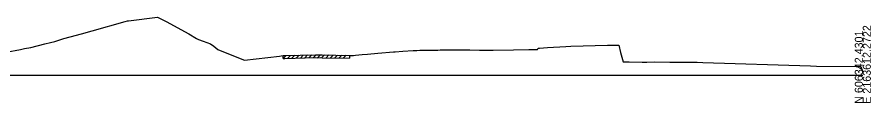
# Model space of a CAD drawing. Extents: x -26 to 6803, y -10 to 19606.
# Drawn here: x 6504.2 to 6802.8, y 4990.3 to 5020.3 of the extents above; entities that cross this region are included whole.
import ezdxf

# ---------------------------------------------------------------- set-up
doc = ezdxf.new("R2010")
doc.units = 0
for name, color, linetype in [('RD_GPK_XS_Cell', 7, 'Continuous'), ('RD_XS_ExGround', 7, 'Continuous'), ('RD_XS_ExPaveRet', 7, 'Continuous')]:
    doc.layers.add(name, color=color, linetype=linetype)

msp = doc.modelspace()

# ---------------------------------------------------------------- linework, layer by layer
at = {"layer": 'RD_GPK_XS_Cell'}
msp.add_line((6400, 5000), (6800, 5000), dxfattribs=at)
at = {"layer": 'RD_XS_ExGround'}
msp.add_lwpolyline([(6500.38, 5008), (6505.36, 5008.99), (6506.75, 5009.33), (6508.99, 5009.72), (6513.89, 5010.95), (6515.88, 5011.48), (6517.39, 5011.8), (6520.54, 5012.88), (6522.74, 5013.36), (6526.78, 5014.46), (6530.51, 5015.49), (6542.06, 5018.82), (6542.83, 5019.01), (6543.17, 5019.04), (6553.31, 5020.31), (6556.33, 5018.76), (6564.24, 5014.5), (6567.02, 5012.81), (6567.63, 5012.49), (6569.35, 5011.84), (6571.87, 5011), (6572.97, 5010.16), (6574.48, 5008.99), (6579.92, 5006.75), (6583.76, 5005.23), (6595.99, 5006.69), (6596.61, 5006.74), (6597.3, 5006.83), (6597.85, 5006.84), (6608.6, 5007.13), (6609.16, 5007.1), (6610.19, 5007.14), (6610.89, 5007.12), (6620.51, 5006.91), (6621.25, 5006.92), (6621.89, 5006.93), (6622.62, 5007), (6623.76, 5007.11), (6624.9, 5007.23), (6626.76, 5007.4), (6630.44, 5007.71), (6635.81, 5008.11), (6636.47, 5008.14), (6639.16, 5008.41), (6642.7, 5008.61), (6643.98, 5008.68), (6645.05, 5008.72), (6645.56, 5008.74), (6646.57, 5008.76), (6648.46, 5008.8), (6649.99, 5008.8), (6651.34, 5008.8), (6652.19, 5008.81), (6654.02, 5008.83), (6654.51, 5008.84), (6656.8, 5008.86), (6658.06, 5008.87), (6659.37, 5008.86), (6662.51, 5008.81), (6665.9, 5008.74), (6668.85, 5008.74), (6670.69, 5008.72), (6677.83, 5008.82), (6683.19, 5008.96), (6684.44, 5008.99), (6685.01, 5009.01), (6686.26, 5008.97), (6686.45, 5009.47), (6686.89, 5009.47), (6689.7, 5009.67), (6696.16, 5010.03), (6697.85, 5010.14), (6710.66, 5010.47), (6713.77, 5010.53), (6714.62, 5010.53), (6715.25, 5007.95), (6716.2, 5004.61), (6718.34, 5004.68), (6722.82, 5004.5), (6724.52, 5004.55), (6727.15, 5004.62), (6732.48, 5004.54), (6737.33, 5004.53), (6742.1, 5004.55), (6744.02, 5004.46), (6781.67, 5003.23), (6783.84, 5003.16), (6797.67, 5002.99), (6798.88, 5002.99), (6799.26, 5002.99), (6800, 5001.01)], dxfattribs=at)
at = {"layer": 'RD_XS_ExPaveRet'}
for p, q in [((6597.3, 5005.83), (6598.32, 5006.85)), ((6597.3, 5005.83), (6597.3, 5006.83)), ((6597.3, 5005.83), (6597.85, 5005.84)), ((6597.3, 5005.83), (6597.3, 5005.83)), ((6597.85, 5005.84), (6608.6, 5006.13)), ((6598.8, 5005.87), (6599.82, 5006.89)), ((6600.3, 5005.91), (6601.32, 5006.94)), ((6601.8, 5005.95), (6602.82, 5006.98)), ((6603.3, 5005.99), (6604.32, 5007.02)), ((6604.8, 5006.03), (6605.82, 5007.06)), ((6606.3, 5006.07), (6607.32, 5007.1)), ((6607.8, 5006.11), (6608.81, 5007.12)), ((6608.6, 5006.13), (6609.16, 5006.1)), ((6609.16, 5006.1), (6610.19, 5006.14)), ((6609.3, 5006.11), (6610.32, 5007.14)), ((6610.19, 5006.14), (6610.89, 5006.12)), ((6610.8, 5006.13), (6611.77, 5007.1)), ((6610.89, 5006.12), (6620.51, 5005.91)), ((6612.3, 5006.09), (6613.27, 5007.07)), ((6613.8, 5006.06), (6614.77, 5007.04)), ((6615.3, 5006.03), (6616.27, 5007.01)), ((6616.8, 5005.99), (6617.77, 5006.97)), ((6618.3, 5005.96), (6619.27, 5006.94)), ((6620.51, 5006.91), (6620.51, 5005.91)), ((6620.51, 5005.91), (6620.51, 5005.91))]:
    msp.add_line(p, q, dxfattribs=at)

# ---------------------------------------------------------------- texts
at = {"layer": 'RD_GPK_XS_Cell'}
for s, p in [('E 2163612.2722', (6802.8, 4990)), ('N 606342.4301', (6800, 4990))]:
    msp.add_text(s, height=2.8, rotation=90, dxfattribs=at).set_placement(p)

doc.saveas('drawing.dxf')
